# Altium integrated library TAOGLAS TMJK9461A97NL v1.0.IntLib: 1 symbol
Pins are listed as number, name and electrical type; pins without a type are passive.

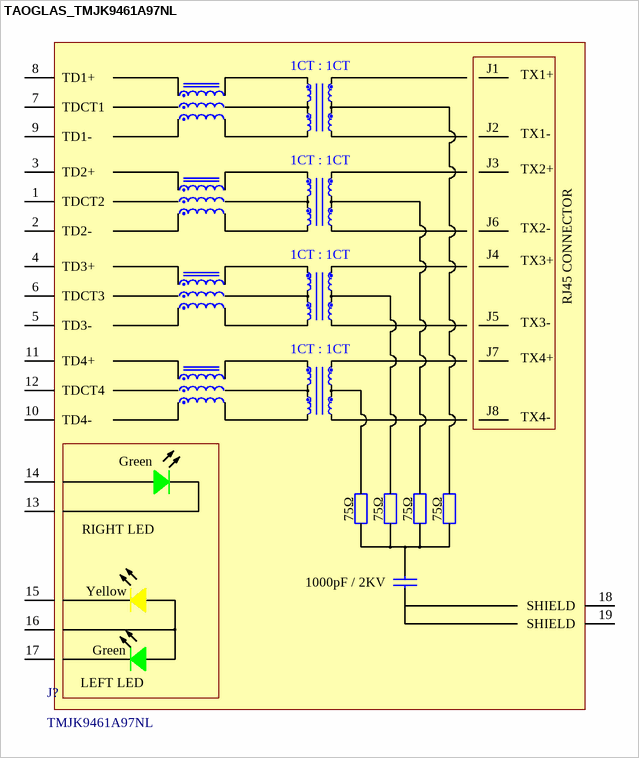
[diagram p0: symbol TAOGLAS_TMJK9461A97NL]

## TAOGLAS_TMJK9461A97NL
designator J?, comment TMJK9461A97NL
RJ45 connector with integrated magnetics 10G Base-T Single Port Tab-UP with right angle THT mount and LEDs; ComponentLibStatus: Created; MFG: Taoglas; Temp_High: +85C; Temp_Low: -40C
footprint TAOGLAS_TMJK9461A97NL (RJ45 connector with integrated magnetics 10G Base-T Single Port Tab-UP with right angle THT mount and LEDs)
pins: 1 TDCT2, 2 TD2-, 3 TD2+, 4 TD3+, 5 TD3-, 6 TDCT3, 7 TDCT1, 8 TD1+, 9 TD1-, 10 TD4-, 11 TD4+, 12 TDCT4, 13, 14, 15, 16, 17, 18 SHIELD, 19 SHIELD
